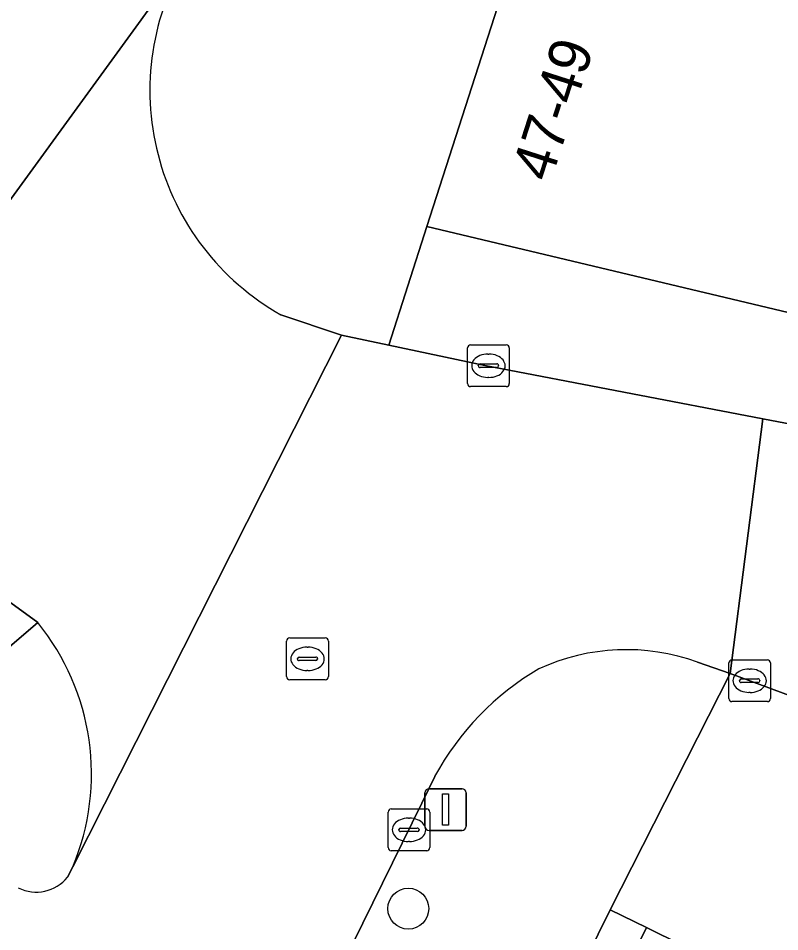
# Model space of a CAD drawing. Extents: x 160102 to 160934, y 382045 to 382923.
# Drawn here: x 160341.42 to 160359.67, y 382326.59 to 382348.47 of the extents above; entities that cross this region are included whole.
import ezdxf

# ---------------------------------------------------------------- set-up
doc = ezdxf.new("R2010")
doc.units = 0
for name, color, linetype in [('IMGEO_Boom', 7, 'Continuous'), ('IMGEO_Erf', 7, 'Continuous'), ('IMGEO_Kolk', 7, 'Continuous'), ('IMGEO_Lichtmast', 7, 'Continuous'), ('IMGEO_Pand', 7, 'Continuous'), ('IMGEO_Pand_nummerreeks', 7, 'Continuous'), ('IMGEO_Rijbaan_lokaal_open', 7, 'Continuous'), ('IMGEO_Rioolput', 7, 'Continuous'), ('IMGEO_Voetpad_open', 7, 'Continuous')]:
    doc.layers.add(name, color=color, linetype=linetype)

msp = doc.modelspace()

# ---------------------------------------------------------------- linework, layer by layer
at = {"layer": 'IMGEO_Boom'}
msp.add_circle((160350.766, 382327.144), 0.489, dxfattribs=at)
at = {"layer": 'IMGEO_Erf'}
msp.add_lwpolyline([(160339.708, 382292.754), (160342.51, 382298.425), (160345.39, 382304.255), (160346.664, 382306.833), (160346.446, 382306.941), (160347.607, 382309.29), (160347.863, 382309.164), (160348.241, 382309.929), (160348.431, 382310.314), (160348.183, 382310.437), (160349.334, 382312.766), (160349.543, 382312.662), (160350.864, 382315.335), (160353.694, 382321.065), (160356.473, 382326.689), (160355.602, 382327.113), (160338.853, 382293.188)], close=True, dxfattribs=at)
at = {"layer": 'IMGEO_Kolk'}
for p, q in [((160352.185, 382339.722), (160352.185, 382340.574)), ((160352.26, 382340.648), (160353.112, 382340.648)), ((160353.186, 382340.574), (160353.186, 382339.722)), ((160352.673, 382340.428), (160352.698, 382340.428)), ((160352.444, 382340.142), (160352.444, 382340.154)), ((160352.487, 382340.191), (160352.885, 382340.191)), ((160352.928, 382340.154), (160352.928, 382340.142)), ((160352.882, 382340.105), (160352.484, 382340.105)), ((160352.696, 382339.868), (160352.671, 382339.868)), ((160353.112, 382339.648), (160352.26, 382339.648)), ((160358.443, 382332.177), (160358.443, 382333.029)), ((160358.518, 382333.103), (160359.37, 382333.103)), ((160359.444, 382333.029), (160359.444, 382332.177)), ((160358.931, 382332.883), (160358.956, 382332.883)), ((160358.702, 382332.597), (160358.702, 382332.609)), ((160359.14, 382332.56), (160358.742, 382332.56)), ((160358.745, 382332.646), (160359.143, 382332.646)), ((160359.186, 382332.609), (160359.186, 382332.597)), ((160358.954, 382332.323), (160358.929, 382332.323)), ((160359.37, 382332.103), (160358.518, 382332.103)), ((160350.281, 382328.606), (160350.281, 382329.458)), ((160350.356, 382329.532), (160351.208, 382329.532)), ((160351.282, 382329.458), (160351.282, 382328.606)), ((160350.769, 382329.312), (160350.794, 382329.312)), ((160350.54, 382329.026), (160350.54, 382329.038)), ((160350.978, 382328.989), (160350.58, 382328.989)), ((160350.583, 382329.075), (160350.981, 382329.075)), ((160351.024, 382329.038), (160351.024, 382329.026)), ((160350.792, 382328.752), (160350.767, 382328.752)), ((160351.208, 382328.532), (160350.356, 382328.532))]:
    msp.add_line(p, q, dxfattribs=at)
for points in [[(160352.185, 382339.722), (160352.185, 382340.574)], [(160352.26, 382340.648), (160353.112, 382340.648)], [(160353.186, 382340.574), (160353.186, 382339.722)], [(160353.112, 382339.648), (160352.26, 382339.648)], [(160358.443, 382332.177), (160358.443, 382333.029)], [(160358.518, 382333.103), (160359.37, 382333.103)], [(160359.444, 382333.029), (160359.444, 382332.177)], [(160359.37, 382332.103), (160358.518, 382332.103)], [(160350.281, 382328.606), (160350.281, 382329.458)], [(160350.356, 382329.532), (160351.208, 382329.532)], [(160351.282, 382329.458), (160351.282, 382328.606)], [(160351.208, 382328.532), (160350.356, 382328.532)]]:
    msp.add_lwpolyline(points, dxfattribs=at)
for centre, radius, start, end in [((160352.262, 382340.572), 0.0765, 91.552, 178.448), ((160352.262, 382340.572), 0.0765, 91.552, 178.448), ((160353.11, 382340.572), 0.0765, 1.552, 88.448), ((160353.11, 382340.572), 0.0765, 1.552, 88.448), ((160352.484, 382340.151), 0.0403, 85.8775, 175.7526), ((160352.481, 382340.141), 0.0366, 178.938, 274.7102), ((160352.885, 382340.148), 0.043, 264.8664, 352.4533), ((160352.889, 382340.153), 0.0386, 1.7309, 96.639), ((160352.262, 382339.724), 0.0765, 181.552, 268.448), ((160352.262, 382339.724), 0.0765, 181.552, 268.448), ((160353.11, 382339.724), 0.0765, 271.552, 358.448), ((160353.11, 382339.724), 0.0765, 271.552, 358.448), ((160358.52, 382333.027), 0.0765, 91.552, 178.448), ((160358.52, 382333.027), 0.0765, 91.552, 178.448), ((160359.368, 382333.027), 0.0765, 1.552, 88.448), ((160359.368, 382333.027), 0.0765, 1.552, 88.448), ((160358.742, 382332.606), 0.0403, 85.8775, 175.7526), ((160358.739, 382332.596), 0.0366, 178.938, 274.7102), ((160359.143, 382332.603), 0.043, 264.8664, 352.4533), ((160359.147, 382332.608), 0.0386, 1.7309, 96.639), ((160358.52, 382332.179), 0.0765, 181.552, 268.448), ((160358.52, 382332.179), 0.0765, 181.552, 268.448), ((160359.368, 382332.179), 0.0765, 271.552, 358.448), ((160359.368, 382332.179), 0.0765, 271.552, 358.448), ((160350.358, 382329.456), 0.0765, 91.552, 178.448), ((160350.358, 382329.456), 0.0765, 91.552, 178.448), ((160351.206, 382329.456), 0.0765, 1.552, 88.448), ((160351.206, 382329.456), 0.0765, 1.552, 88.448), ((160350.58, 382329.035), 0.0403, 85.8775, 175.7526), ((160350.577, 382329.025), 0.0366, 178.938, 274.7102), ((160350.981, 382329.032), 0.043, 264.8664, 352.4533), ((160350.985, 382329.037), 0.0386, 1.7309, 96.639), ((160350.358, 382328.608), 0.0765, 181.552, 268.448), ((160350.358, 382328.608), 0.0765, 181.552, 268.448), ((160351.206, 382328.608), 0.0765, 271.552, 358.448), ((160351.206, 382328.608), 0.0765, 271.552, 358.448)]:
    msp.add_arc(centre, radius, start, end, dxfattribs=at)
for centre, major_axis, ratio, start_param, end_param in [((160352.672, 382340.148), (-0.387, 0.002), 0.722429, 4.712389, 7.853982), ((160352.697, 382340.148), (-0.39, 0.002), 0.717154, 1.570796, 4.712389), ((160358.93, 382332.603), (-0.387, 0.002), 0.722429, 4.712389, 7.853982), ((160358.955, 382332.603), (-0.39, 0.002), 0.717154, 1.570796, 4.712389), ((160350.768, 382329.032), (-0.387, 0.002), 0.722429, 4.712389, 7.853982), ((160350.793, 382329.032), (-0.39, 0.002), 0.717154, 1.570796, 4.712389)]:
    msp.add_ellipse(centre, major_axis=major_axis, ratio=ratio, start_param=start_param, end_param=end_param, dxfattribs=at)
at = {"layer": 'IMGEO_Lichtmast'}
for p, q in [((160351.163, 382329.117), (160351.163, 382329.917)), ((160351.163, 382329.917), (160351.163, 382329.117)), ((160351.263, 382330.017), (160352.053, 382330.017)), ((160352.053, 382330.017), (160351.263, 382330.017)), ((160352.153, 382329.917), (160352.153, 382329.117)), ((160352.153, 382329.117), (160352.153, 382329.917)), ((160352.053, 382329.017), (160351.263, 382329.017)), ((160351.263, 382329.017), (160352.053, 382329.017))]:
    msp.add_line(p, q, dxfattribs=at)
msp.add_lwpolyline([(160351.583, 382329.892), (160351.733, 382329.892), (160351.733, 382329.142), (160351.583, 382329.142), (160351.583, 382329.892)], dxfattribs=at)
for centre, start, end in [((160351.263, 382329.917), 90, 180), ((160351.263, 382329.917), 90, 180), ((160352.053, 382329.917), 0, 90), ((160352.053, 382329.917), 360, 90), ((160351.263, 382329.117), 180, 270), ((160351.263, 382329.117), 180, 270), ((160352.053, 382329.117), 270, 0), ((160352.053, 382329.117), 270, 0)]:
    msp.add_arc(centre, 0.1, start, end, dxfattribs=at)
at = {"layer": 'IMGEO_Pand'}
for points in [[(160381.561, 382356.703), (160380.205, 382358.935), (160378.56, 382361.643), (160377.35, 382363.459), (160370.025, 382365.327), (160363.301, 382361.295), (160361.172, 382353.557), (160361.542, 382353.21), (160359.757, 382352.841), (160353.832, 382351.615), (160351.214, 382343.481), (160360.037, 382341.38), (160367.672, 382339.562), (160368.598, 382340.564), (160372.136, 382344.347), (160371.738, 382344.497), (160371.998, 382345.43), (160372.931, 382345.171), (160379.619, 382349.085)], [(160362.523, 382323.7), (160361.552, 382324.18), (160359.856, 382325.018), (160356.473, 382326.689), (160353.694, 382321.065), (160359.744, 382318.076)]]:
    msp.add_lwpolyline(points, close=True, dxfattribs=at)
at = {"layer": 'IMGEO_Rijbaan_lokaal_open'}
for points in [[(160330.87, 382342.067), (160334.349, 382339.545), (160335.38, 382338.728), (160336.638, 382337.813), (160345.495, 382349.987)], [(160345.495, 382349.987), (160336.638, 382337.813), (160341.888, 382333.998)], [(160342.728, 382328.146), (160349.162, 382340.88), (160347.715, 382341.368)], [(160357.694, 382333.049), (160358.478, 382332.777), (160359.259, 382338.878), (160352.597, 382340.151), (160350.299, 382340.639), (160349.162, 382340.88), (160342.728, 382328.146), (160342.601, 382327.901)], [(160391.886, 382326.191), (160382.828, 382331.994), (160381.398, 382332.855), (160367.385, 382337.325), (160359.259, 382338.878), (160358.478, 382332.777), (160374.104, 382326.98), (160380.469, 382324.649)], [(160351.092, 382329.667), (160351.398, 382330.311)], [(160339.322, 382305.969), (160340.981, 382309.131), (160351.092, 382329.667)]]:
    msp.add_lwpolyline(points, dxfattribs=at)
for centre, radius, start, end in [((160350.745, 382346.744), 6.171, 148.2945, 240.593), ((160337.421, 382330.371), 5.754, 337.2583, 39.0787), ((160355.989, 382328.325), 5.022, 70.1522, 114.641), ((160357.276, 382327.118), 6.69, 120.3623, 151.4887), ((160341.852, 382328.5), 0.959, 243.3103, 321.3563)]:
    msp.add_arc(centre, radius, start, end, dxfattribs=at)
at = {"layer": 'IMGEO_Rioolput'}
for p, q in [((160347.851, 382332.702), (160347.851, 382333.554)), ((160347.926, 382333.628), (160348.778, 382333.628)), ((160348.852, 382333.554), (160348.852, 382332.702)), ((160348.339, 382333.408), (160348.364, 382333.408)), ((160348.11, 382333.122), (160348.11, 382333.134)), ((160348.153, 382333.171), (160348.551, 382333.171)), ((160348.594, 382333.134), (160348.594, 382333.122)), ((160348.548, 382333.085), (160348.15, 382333.085)), ((160348.362, 382332.848), (160348.337, 382332.848)), ((160348.778, 382332.628), (160347.926, 382332.628))]:
    msp.add_line(p, q, dxfattribs=at)
for points in [[(160347.851, 382332.702), (160347.851, 382333.554)], [(160347.926, 382333.628), (160348.778, 382333.628)], [(160348.852, 382333.554), (160348.852, 382332.702)], [(160348.778, 382332.628), (160347.926, 382332.628)]]:
    msp.add_lwpolyline(points, dxfattribs=at)
for centre, radius, start, end in [((160347.928, 382333.552), 0.0765, 91.552, 178.448), ((160347.928, 382333.552), 0.0765, 91.552, 178.448), ((160348.776, 382333.552), 0.0765, 1.552, 88.448), ((160348.776, 382333.552), 0.0765, 1.552, 88.448), ((160348.15, 382333.131), 0.0403, 85.8775, 175.7526), ((160348.147, 382333.121), 0.0366, 178.938, 274.7102), ((160348.551, 382333.128), 0.043, 264.8664, 352.4533), ((160348.555, 382333.133), 0.0386, 1.7309, 96.639), ((160347.928, 382332.704), 0.0765, 181.552, 268.448), ((160347.928, 382332.704), 0.0765, 181.552, 268.448), ((160348.776, 382332.704), 0.0765, 271.552, 358.448), ((160348.776, 382332.704), 0.0765, 271.552, 358.448)]:
    msp.add_arc(centre, radius, start, end, dxfattribs=at)
for centre, major_axis, ratio, start_param, end_param in [((160348.338, 382333.128), (-0.387, 0.002), 0.722429, 4.712389, 7.853982), ((160348.363, 382333.128), (-0.39, 0.002), 0.717154, 1.570796, 4.712389)]:
    msp.add_ellipse(centre, major_axis=major_axis, ratio=ratio, start_param=start_param, end_param=end_param, dxfattribs=at)
at = {"layer": 'IMGEO_Voetpad_open'}
for points in [[(160347.715, 382341.368), (160349.162, 382340.88), (160350.299, 382340.639), (160351.214, 382343.481), (160353.832, 382351.615), (160359.757, 382352.841), (160359.514, 382354.017), (160353.465, 382352.766), (160365.714, 382369.738), (160366.423, 382370.661), (160367.539, 382372.279), (160370.489, 382375.889), (160371.662, 382377.478), (160374.55, 382381.391), (160376.634, 382379.866), (160378.446, 382382.312), (160380.114, 382384.731)], [(160413.948, 382356.505), (160412.873, 382357.286), (160412.017, 382357.908), (160404.649, 382363.264), (160401.179, 382360.906), (160397.583, 382358.462), (160395.957, 382357.357), (160393.722, 382355.935), (160391.201, 382354.323), (160386.481, 382351.243), (160384.413, 382349.893), (160368.603, 382339.576), (160368.34, 382339.404), (160367.672, 382339.562), (160360.037, 382341.38), (160351.214, 382343.481), (160350.299, 382340.639), (160352.597, 382340.151), (160359.259, 382338.878), (160367.385, 382337.325)], [(160326.653, 382341.048), (160328.228, 382339.913), (160339.392, 382331.862), (160341.888, 382333.998), (160336.638, 382337.813), (160335.38, 382338.728), (160334.349, 382339.545)], [(160341.888, 382333.998), (160339.392, 382331.862)], [(160355.602, 382327.113), (160358.478, 382332.777), (160357.694, 382333.049)], [(160380.469, 382324.649), (160374.104, 382326.98), (160358.478, 382332.777), (160355.602, 382327.113), (160356.473, 382326.689), (160359.856, 382325.018), (160361.552, 382324.18)], [(160351.398, 382330.311), (160351.092, 382329.667), (160340.981, 382309.131), (160339.322, 382305.969)], [(160342.601, 382327.901), (160342.728, 382328.146)], [(160335.504, 382287.5), (160338.853, 382293.188), (160355.602, 382327.113)]]:
    msp.add_lwpolyline(points, dxfattribs=at)
for centre, radius, start, end in [((160350.745, 382346.744), 6.171, 148.2945, 240.593), ((160337.421, 382330.371), 5.754, 337.2583, 39.0787), ((160355.989, 382328.325), 5.022, 70.1522, 114.641), ((160357.276, 382327.118), 6.69, 120.3623, 151.4887), ((160341.852, 382328.5), 0.959, 243.3103, 321.3563)]:
    msp.add_arc(centre, radius, start, end, dxfattribs=at)

# ---------------------------------------------------------------- texts
at = {"layer": 'IMGEO_Pand_nummerreeks'}
msp.add_text('47-49', height=1, rotation=72.1583, dxfattribs=at).set_placement((160354.174, 382344.517))

doc.saveas('drawing.dxf')
